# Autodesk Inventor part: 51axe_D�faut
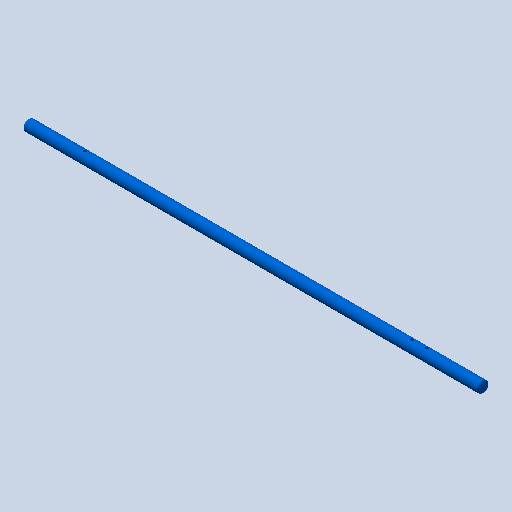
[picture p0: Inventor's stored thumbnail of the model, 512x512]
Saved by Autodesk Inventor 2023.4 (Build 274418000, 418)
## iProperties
Created: 2011-01
Part Number: 51axe_D�faut
Document SubType Name: Modeling
Designer: eric
Density: 1 g/cm^3
Mass: 54.2276 g
Surface Area: 186.426 cm^2
Volume: 54.2276 cm^3
Material: Générique
Appearance: 0,128,255_1
Author: eric
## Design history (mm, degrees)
feature "Base1"
node "Corps solides"
node "Corps surfaciques"
node "Solide1"
